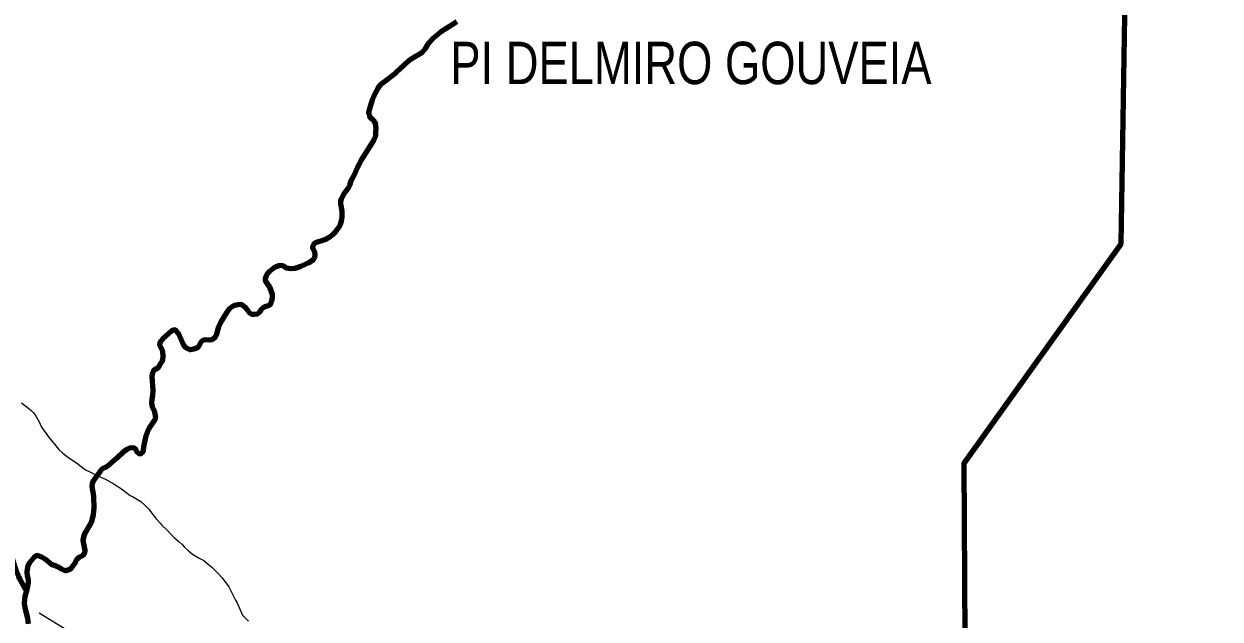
# Model space of a CAD drawing. Extents: x 553962 to 842807, y 8883888 to 9032388.
# Drawn here: x 621552 to 638482, y 8956198 to 8964625 of the extents above; entities that cross this region are included whole.
import ezdxf

# ---------------------------------------------------------------- set-up
doc = ezdxf.new("R2010")
doc.units = 0
doc.header["$LTSCALE"] = 160
doc.linetypes.add('LONG_DASH_SHORT_DASH', pattern=[9.9, 6, -1.2, 1.5, -1.2])
for name, color, linetype, lineweight in [('15', 7, 'Continuous', 25), ('2', 7, 'Continuous', 13), ('21', 7, 'Continuous', 25), ('27', 7, 'Continuous', 90), ('34', 7, 'LONG_DASH_SHORT_DASH', 60)]:
    doc.layers.add(name, color=color, linetype=linetype, lineweight=lineweight)

msp = doc.modelspace()

# ---------------------------------------------------------------- linework, layer by layer
at = {"layer": '15'}
msp.add_lwpolyline([(621517.4, 8959257.6), (621620.6, 8959177.6), (621652, 8959151.6), (621681.1, 8959122.6), (621709.4, 8959090.6), (621730.8, 8959055.6), (621766, 8958989.6), (621797.6, 8958926.5), (621816.7, 8958894.5), (621897.9, 8958779.4), (622047.1, 8958598.4), (622104.4, 8958547.4), (622189, 8958482.4), (622295.2, 8958408.5), (622402.8, 8958323.5), (622432, 8958306.5), (622464.2, 8958290.6), (622503.3, 8958272.6), (622656.9, 8958198.7), (622695.9, 8958184.8), (622781.7, 8958137.8), (622814.5, 8958116.8), (622845, 8958100.9), (622933, 8958040.9), (622994, 8957997), (623055.6, 8957949), (623090.1, 8957935), (623208.6, 8957861.1), (623261.3, 8957811.1), (623293.1, 8957783.1), (623319, 8957753.1), (623370.1, 8957684.1), (623394.1, 8957657.1), (623423, 8957618), (623480.8, 8957556), (623503.5, 8957528), (623577.3, 8957455), (623634.3, 8957397), (623656.2, 8957377), (623681.5, 8957349), (623715.2, 8957318), (623746.4, 8957294), (623796.4, 8957250.1), (623820, 8957220), (623881.1, 8957162.1), (623907.7, 8957139.1), (623938.3, 8957116.1), (624032.6, 8957060.1), (624097.3, 8957025.2), (624126.4, 8957005.2), (624156.6, 8956982.2), (624209.6, 8956933.2), (624300.1, 8956843.2), (624356.6, 8956783.2), (624452.3, 8956653.2), (624547.5, 8956464), (624563.3, 8956437), (624643.8, 8956253.8), (624732.1, 8956169.8)], dxfattribs=at)
at = {"layer": '21'}
for points in [[(627680.5, 8964655.8), (627612, 8964609.6), (627536.8, 8964566.4), (627449.5, 8964509.2), (627333.7, 8964414.8), (627272.4, 8964348.6), (627225, 8964267.4), (627185.5, 8964217.3), (627032.1, 8964127.9), (627004.7, 8964107.8), (626815.8, 8963934.3), (626629.8, 8963789.7), (626590.1, 8963751.6), (626566.7, 8963720.5), (626506, 8963608.3), (626480.1, 8963551.1), (626439.9, 8963406.8), (626430.6, 8963358.8), (626441.2, 8963331.8), (626448.8, 8963299.7), (626457.1, 8963293.7), (626491.3, 8963272.5), (626505.7, 8963251), (626515.9, 8963242.8), (626529.7, 8963201.7), (626531.3, 8963131.3), (626529.2, 8963109.8), (626529.5, 8963038.6), (626501.7, 8962971.9), (626473.9, 8962938.6), (626318.3, 8962688.6), (626296, 8962638.6), (626262.7, 8962577.5), (626240.4, 8962522), (626212.7, 8962460.8), (626174.8, 8962393.8), (626164.1, 8962350.8), (626134.9, 8962291.6), (626076.5, 8962209.4), (626043, 8962145.2), (626033.4, 8962116.2), (626031, 8962086.1), (626050.8, 8961971), (626052.2, 8961893.9), (626043.5, 8961829.8), (626030, 8961782.7), (626007.6, 8961741.6), (625960.4, 8961681.4), (625923.5, 8961643.3), (625862.9, 8961595.1), (625822.7, 8961574), (625681.1, 8961524.7), (625666.2, 8961515.7), (625650, 8961497.6), (625640, 8961477.6), (625636.3, 8961455.5), (625664.5, 8961397.5), (625669.9, 8961359.4), (625663.1, 8961316.3), (625644, 8961283.3), (625582.5, 8961243.1), (625473.5, 8961191.8)], [(625473.5, 8961191.8), (625385.3, 8961162.7), (625335.4, 8961158.6), (625297, 8961160.5), (625268.2, 8961168.5), (625214.1, 8961198.5), (625173.4, 8961205.4), (625117.9, 8961186.3), (625078.9, 8961163.2), (625027.5, 8961119), (625000.9, 8961089), (624975.3, 8961048.8), (624966.1, 8961016.8), (624966.2, 8960999.8), (624973, 8960982.7), (625029.9, 8960900.7), (625064.6, 8960798.6), (625067, 8960768.6), (625061.1, 8960709.5), (625046, 8960671.4), (625027.5, 8960644.3), (625011.3, 8960634.2), (624961, 8960619.2), (624936.3, 8960606.1), (624912, 8960582), (624879.5, 8960536.9), (624854.3, 8960516.8), (624811.3, 8960509.7), (624784.5, 8960512.7), (624750.7, 8960527.7), (624725.6, 8960556.7), (624680, 8960618.7), (624640.1, 8960648.7), (624615.7, 8960653.7), (624577.3, 8960648.6), (624531.2, 8960635.5), (624496.8, 8960619.4)], [(624496.8, 8960619.4), (624466.5, 8960595.3), (624466.5, 8960595.3), (624418.2, 8960536.2), (624388.4, 8960493.1), (624334.1, 8960398.8), (624304.9, 8960334.7), (624271.6, 8960219.4), (624255.9, 8960184.4), (624237, 8960167.3), (624209.4, 8960152.2), (624177.8, 8960149.2), (624105.6, 8960150.1), (624084, 8960144), (624056.4, 8960117.9), (624029.7, 8960062.8), (624008.5, 8960040.7), (623952.6, 8960017.6), (623906.6, 8960011.5), (623879.7, 8960018.5), (623839.9, 8960041.5), (623809.1, 8960087.5), (623742.1, 8960236.6), (623708.6, 8960280.6), (623691, 8960291.6), (623663.5, 8960287.6), (623642.3, 8960274.5), (623518.1, 8960166.2), (623487.9, 8960132.1), (623473.9, 8960107), (623469.3, 8960080), (623503, 8960016.9), (623511.8, 8959991.9), (623518.8, 8959918.8), (623515.2, 8959871.7), (623503, 8959841.6), (623483.8, 8959814.6), (623458.3, 8959764.4), (623435.3, 8959743.4), (623405.8, 8959733.3), (623380.1, 8959708.2), (623370, 8959684.2), (623363, 8959639.1), (623374, 8959437.8), (623371.3, 8959365.7), (623362.7, 8959309.6), (623359.5, 8959254.5), (623367, 8959203.4), (623399.7, 8959131.4), (623414.8, 8959045.2), (623404.2, 8959022.2), (623338.3, 8958926.9), (623315, 8958880.8), (623272.9, 8958769.6), (623243.1, 8958633.3), (623241.6, 8958590.3), (623234, 8958561.2), (623207.1, 8958537.1), (623180.9, 8958538.1), (623154, 8958559.1), (623142.4, 8958588.1), (623129.2, 8958606.1), (623114.3, 8958616.1), (623091.3, 8958624.1), (623048.1, 8958618)], [(623048.1, 8958618), (623008.6, 8958598.9), (622961, 8958563.8), (622867, 8958474.5), (622765.3, 8958385.2), (622710.3, 8958350.1), (622672.6, 8958336), (622645.8, 8958310.9), (622635.8, 8958292.8), (622526.4, 8958139.4), (622516.5, 8958114.4), (622511.7, 8958078.3), (622515.3, 8958048.3), (622533.3, 8957971.2), (622537.7, 8957930.1), (622539.2, 8957771.9), (622532.6, 8957678.7), (622519.6, 8957617.6), (622503, 8957566.5), (622414.7, 8957413.1), (622392.8, 8957358), (622387.2, 8957313.9), (622413.1, 8957173.7), (622412, 8957144.7), (622401.3, 8957121.6), (622379.3, 8957091.6), (622329.5, 8957067.4), (622303.6, 8957046.4), (622292.3, 8957028.3), (622277.2, 8956988.2), (622224.7, 8956922.1), (622199.4, 8956902), (622173.6, 8956888.9), (622144.5, 8956882.9), (622124.1, 8956884.8), (622082.2, 8956903.8), (622023.4, 8956940.8)], [(622023.4, 8956940.8), (621940, 8956970.7), (621852.9, 8957044.7), (621852.9, 8957044.7), (621788.3, 8957084.6), (621747.1, 8957098.6), (621722, 8957094.5), (621699.9, 8957079.5), (621630.5, 8956993.2), (621609.1, 8956955.1), (621593, 8956869), (621597.7, 8956809.9), (621609.5, 8956752.8), (621610.3, 8956716.8), (621596.7, 8956635.6), (621564.2, 8956517.4), (621555.7, 8956425.2), (621563.4, 8956363.1), (621602.1, 8956205), (621612.3, 8956132.8)]]:
    msp.add_lwpolyline(points, dxfattribs=at)
at = {"layer": '27'}
for points in [[(637260.6, 8972975.8), (637076.8, 8961505.7), (634855.7, 8958401.3), (634875.3, 8955110.3)], [(627680.5, 8964655.8), (627612, 8964609.6), (627536.8, 8964566.4), (627449.5, 8964509.2), (627333.7, 8964414.8), (627272.4, 8964348.6), (627225, 8964267.4), (627185.5, 8964217.3), (627032.1, 8964127.9), (627004.7, 8964107.8), (626815.8, 8963934.3), (626629.8, 8963789.7), (626590.1, 8963751.6), (626566.7, 8963720.5), (626506, 8963608.3), (626480.1, 8963551.1), (626439.9, 8963406.8), (626430.6, 8963358.8), (626441.2, 8963331.8), (626448.8, 8963299.7), (626457.1, 8963293.7), (626491.3, 8963272.5), (626505.7, 8963251), (626515.9, 8963242.8), (626529.7, 8963201.7), (626531.3, 8963131.3), (626529.2, 8963109.8), (626529.5, 8963038.6), (626501.7, 8962971.9), (626473.9, 8962938.6), (626318.3, 8962688.6), (626296, 8962638.6), (626262.7, 8962577.5), (626240.4, 8962522), (626212.7, 8962460.8), (626174.8, 8962393.8), (626164.1, 8962350.8), (626134.9, 8962291.6), (626076.5, 8962209.4), (626043, 8962145.2), (626033.4, 8962116.2), (626031, 8962086.1), (626050.8, 8961971), (626052.2, 8961893.9), (626043.5, 8961829.8), (626030, 8961782.7), (626007.6, 8961741.6), (625960.4, 8961681.4), (625923.5, 8961643.3), (625862.9, 8961595.1), (625822.7, 8961574), (625681.1, 8961524.7), (625666.2, 8961515.7), (625650, 8961497.6), (625640, 8961477.6), (625636.3, 8961455.5), (625664.5, 8961397.5), (625669.9, 8961359.4), (625663.1, 8961316.3), (625644, 8961283.3), (625582.5, 8961243.1), (625473.5, 8961191.8)], [(625473.5, 8961191.8), (625385.3, 8961162.7), (625335.4, 8961158.6), (625297, 8961160.5), (625268.2, 8961168.5), (625214.1, 8961198.5), (625173.4, 8961205.4), (625117.9, 8961186.3), (625078.9, 8961163.2), (625027.5, 8961119), (625000.9, 8961089), (624975.3, 8961048.8), (624966.1, 8961016.8), (624966.2, 8960999.8), (624973, 8960982.7), (625029.9, 8960900.7), (625064.6, 8960798.6), (625067, 8960768.6), (625061.1, 8960709.5), (625046, 8960671.4), (625027.5, 8960644.3), (625011.3, 8960634.2), (624961, 8960619.2), (624936.3, 8960606.1), (624912, 8960582), (624879.5, 8960536.9), (624854.3, 8960516.8), (624811.3, 8960509.7), (624784.5, 8960512.7), (624750.7, 8960527.7), (624725.6, 8960556.7), (624680, 8960618.7), (624640.1, 8960648.7), (624615.7, 8960653.7), (624577.3, 8960648.6), (624531.2, 8960635.5), (624496.8, 8960619.4)], [(624496.8, 8960619.4), (624466.5, 8960595.3), (624466.5, 8960595.3), (624418.2, 8960536.2), (624388.4, 8960493.1), (624334.1, 8960398.8), (624304.9, 8960334.7), (624271.6, 8960219.4), (624255.9, 8960184.4), (624237, 8960167.3), (624209.4, 8960152.2), (624177.8, 8960149.2), (624105.6, 8960150.1), (624084, 8960144), (624056.4, 8960117.9), (624029.7, 8960062.8), (624008.5, 8960040.7), (623952.6, 8960017.6), (623906.6, 8960011.5), (623879.7, 8960018.5), (623839.9, 8960041.5), (623809.1, 8960087.5), (623742.1, 8960236.6), (623708.6, 8960280.6), (623691, 8960291.6), (623663.5, 8960287.6), (623642.3, 8960274.5), (623518.1, 8960166.2), (623487.9, 8960132.1), (623473.9, 8960107), (623469.3, 8960080), (623503, 8960016.9), (623511.8, 8959991.9), (623518.8, 8959918.8), (623515.2, 8959871.7), (623503, 8959841.6), (623483.8, 8959814.6), (623458.3, 8959764.4), (623435.3, 8959743.4), (623405.8, 8959733.3), (623380.1, 8959708.2), (623370, 8959684.2), (623363, 8959639.1), (623374, 8959437.8), (623371.3, 8959365.7), (623362.7, 8959309.6), (623359.5, 8959254.5), (623367, 8959203.4), (623399.7, 8959131.4), (623414.8, 8959045.2), (623404.2, 8959022.2), (623338.3, 8958926.9), (623315, 8958880.8), (623272.9, 8958769.6), (623243.1, 8958633.3), (623241.6, 8958590.3), (623234, 8958561.2), (623207.1, 8958537.1), (623180.9, 8958538.1), (623154, 8958559.1), (623142.4, 8958588.1), (623129.2, 8958606.1), (623114.3, 8958616.1), (623091.3, 8958624.1), (623048.1, 8958618)], [(623048.1, 8958618), (623008.6, 8958598.9), (622961, 8958563.8), (622867, 8958474.5), (622765.3, 8958385.2), (622710.3, 8958350.1), (622672.6, 8958336), (622645.8, 8958310.9), (622635.8, 8958292.8), (622526.4, 8958139.4), (622516.5, 8958114.4), (622511.7, 8958078.3), (622515.3, 8958048.3), (622533.3, 8957971.2), (622537.7, 8957930.1), (622539.2, 8957771.9), (622532.6, 8957678.7), (622519.6, 8957617.6), (622503, 8957566.5), (622414.7, 8957413.1), (622392.8, 8957358), (622387.2, 8957313.9), (622413.1, 8957173.7), (622412, 8957144.7), (622401.3, 8957121.6), (622379.3, 8957091.6), (622329.5, 8957067.4), (622303.6, 8957046.4), (622292.3, 8957028.3), (622277.2, 8956988.2), (622224.7, 8956922.1), (622199.4, 8956902), (622173.6, 8956888.9), (622144.5, 8956882.9), (622124.1, 8956884.8), (622082.2, 8956903.8), (622023.4, 8956940.8)], [(622023.4, 8956940.8), (621940, 8956970.7), (621852.9, 8957044.7), (621852.9, 8957044.7), (621788.3, 8957084.6), (621747.1, 8957098.6), (621722, 8957094.5), (621699.9, 8957079.5), (621630.5, 8956993.2), (621609.1, 8956955.1), (621593, 8956869), (621597.7, 8956809.9), (621609.5, 8956752.8), (621610.3, 8956716.8), (621596.7, 8956635.6), (621564.2, 8956517.4), (621555.7, 8956425.2), (621563.4, 8956363.1), (621602.1, 8956205), (621612.3, 8956132.8)]]:
    msp.add_lwpolyline(points, dxfattribs=at)
for points in [[(592698.5, 8977198.4), (599903.5, 8973292.7), (608459.2, 8968138.2), (612674.8, 8965332.6), (616842, 8962096.4), (620005, 8958671.2), (621134, 8957974.7), (621473.4, 8956805.3), (621586.2, 8956597.5)], [(637260.6, 8972975.8), (641524.5, 8971056.2), (652526.1, 8965412.7), (653164.3, 8965062.8), (670790.5, 8953770.1), (686194, 8943929.9), (696283.3, 8937647.1)]]:
    msp.add_spline(points, degree=3, dxfattribs=at)
at = {"layer": '34', "linetype": 'Continuous', "lineweight": 13}
msp.add_lwpolyline([(621765.9, 8956286.7), (632981.1, 8949386.2), (646509.8, 8949098.4)], dxfattribs=at)

# ---------------------------------------------------------------- texts
at = {"layer": '2', "width": 0.8}
msp.add_text('PI DELMIRO GOUVEIA', height=600, dxfattribs=at).set_placement((627586.8, 8963772.2))

doc.saveas('drawing.dxf')
